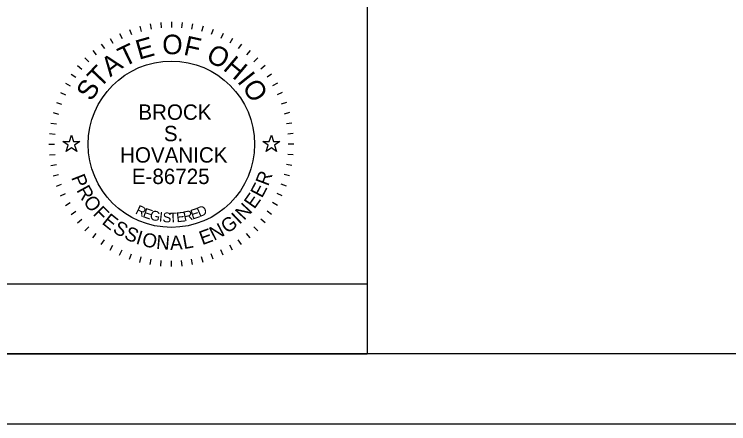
# Model space of a CAD drawing. Extents: x -3.6 to 34, y 0 to 32.8.
# Drawn here: x 23.88 to 28.99, y 0 to 2.93 of the extents above; entities that cross this region are included whole.
import ezdxf

# ---------------------------------------------------------------- set-up
doc = ezdxf.new("R2010")
doc.units = 0
for name, color, linetype in [('SH_Border', 7, 'Continuous'), ('SH_Cut_Line', 7, 'Continuous'), ('SH_Data', 7, 'Continuous'), ('SH_Seal', 7, 'Continuous')]:
    doc.layers.add(name, color=color, linetype=linetype)

msp = doc.modelspace()

# ---------------------------------------------------------------- linework, layer by layer
at = {"layer": 'SH_Border'}
msp.add_lwpolyline([(1.5, 21.5), (33.5, 21.5), (33.5, 0.5), (1.5, 0.5)], close=True, dxfattribs=at)
at = {"layer": 'SH_Cut_Line'}
msp.add_lwpolyline([(0, 0), (34, 0), (34, 22), (0, 22)], close=True, dxfattribs=at)
at = {"layer": 'SH_Data'}
for p in [(26.4, 3.75), (23.6, 0.5)]:
    msp.add_line(p, (26.4, 0.5), dxfattribs=at)
msp.add_lwpolyline([(23.6, 0.5), (23.6, 1), (26.4, 1), (26.4, 0.5)], close=True, dxfattribs=at)
at = {"layer": 'SH_Seal'}
for p, q in [((24.8481, 2.8617), (24.855, 2.8223)), ((24.9237, 2.8717), (24.9272, 2.8318)), ((25, 2.875), (25, 2.835)), ((25.0763, 2.8717), (25.0728, 2.8318)), ((25.1519, 2.8617), (25.145, 2.8223)), ((24.7007, 2.8222), (24.7144, 2.7846)), ((24.7735, 2.8452), (24.7839, 2.8065)), ((25.2265, 2.8452), (25.2161, 2.8065)), ((25.2993, 2.8222), (25.2856, 2.7846)), ((24.6302, 2.793), (24.6471, 2.7568)), ((25.3698, 2.793), (25.3529, 2.7568)), ((24.4981, 2.7168), (24.5211, 2.684)), ((24.5625, 2.7578), (24.5825, 2.7231)), ((25.4375, 2.7578), (25.4175, 2.7231)), ((25.5019, 2.7168), (25.4789, 2.684)), ((24.4376, 2.6703), (24.4633, 2.6396)), ((25.5624, 2.6703), (25.5367, 2.6396)), ((24.3813, 2.6187), (24.4096, 2.5904)), ((25.6187, 2.6187), (25.5904, 2.5904)), ((24.3297, 2.5624), (24.3604, 2.5367)), ((25.6703, 2.5624), (25.6396, 2.5367)), ((24.2832, 2.5019), (24.316, 2.4789)), ((25.7168, 2.5019), (25.684, 2.4789)), ((24.2422, 2.4375), (24.2769, 2.4175)), ((25.7578, 2.4375), (25.7231, 2.4175)), ((24.207, 2.3698), (24.2432, 2.3529)), ((25.793, 2.3698), (25.7568, 2.3529)), ((24.1778, 2.2993), (24.2154, 2.2856)), ((25.8222, 2.2993), (25.7846, 2.2856)), ((24.1548, 2.2265), (24.1935, 2.2161)), ((25.8452, 2.2265), (25.8065, 2.2161)), ((24.1383, 2.1519), (24.1777, 2.145)), ((25.8617, 2.1519), (25.8223, 2.145)), ((24.1283, 2.0763), (24.1682, 2.0728)), ((25.8717, 2.0763), (25.8318, 2.0728)), ((24.125, 2), (24.165, 2)), ((25.875, 2), (25.835, 2)), ((24.1283, 1.9237), (24.1682, 1.9272)), ((25.8717, 1.9237), (25.8318, 1.9272)), ((24.1383, 1.8481), (24.1777, 1.855)), ((25.8617, 1.8481), (25.8223, 1.855)), ((24.1548, 1.7735), (24.1935, 1.7839)), ((25.8452, 1.7735), (25.8065, 1.7839)), ((24.1778, 1.7007), (24.2154, 1.7144)), ((25.8222, 1.7007), (25.7846, 1.7144)), ((24.207, 1.6302), (24.2432, 1.6471)), ((25.793, 1.6302), (25.7568, 1.6471)), ((24.2422, 1.5625), (24.2769, 1.5825)), ((25.7578, 1.5625), (25.7231, 1.5825)), ((24.2832, 1.4981), (24.316, 1.5211)), ((25.7168, 1.4981), (25.684, 1.5211)), ((24.3297, 1.4376), (24.3604, 1.4633)), ((25.6703, 1.4376), (25.6396, 1.4633)), ((24.3813, 1.3813), (24.4096, 1.4096)), ((25.6187, 1.3813), (25.5904, 1.4096)), ((24.4376, 1.3297), (24.4633, 1.3604)), ((25.5624, 1.3297), (25.5367, 1.3604)), ((24.4981, 1.2832), (24.5211, 1.316)), ((25.5019, 1.2832), (25.4789, 1.316)), ((24.5625, 1.2422), (24.5825, 1.2769)), ((24.6302, 1.207), (24.6471, 1.2432)), ((25.3698, 1.207), (25.3529, 1.2432)), ((25.4375, 1.2422), (25.4175, 1.2769)), ((24.7007, 1.1778), (24.7144, 1.2154)), ((24.7735, 1.1548), (24.7839, 1.1935)), ((24.8481, 1.1383), (24.855, 1.1777)), ((25.1519, 1.1383), (25.145, 1.1777)), ((25.2265, 1.1548), (25.2161, 1.1935)), ((25.2993, 1.1778), (25.2856, 1.2154)), ((24.9237, 1.1283), (24.9272, 1.1682)), ((25, 1.125), (25, 1.165)), ((25.0763, 1.1283), (25.0728, 1.1682))]:
    msp.add_line(p, q, dxfattribs=at)
for points in [[(24.2236, 2.02), (24.2705, 2.02), (24.285, 2.0645), (24.2995, 2.02), (24.3464, 2.02), (24.3085, 1.9924), (24.323, 1.9478), (24.285, 1.9754), (24.247, 1.9478), (24.2615, 1.9924)], [(25.6536, 2.02), (25.7005, 2.02), (25.715, 2.0645), (25.7295, 2.02), (25.7764, 2.02), (25.7385, 1.9924), (25.753, 1.9478), (25.715, 1.9754), (25.677, 1.9478), (25.6915, 1.9924)]]:
    msp.add_lwpolyline(points, close=True, dxfattribs=at)
msp.add_circle((25, 2), 0.595, dxfattribs=at)

# ---------------------------------------------------------------- texts
for s, height, rotation, p in [('E', 0.14, 15.7571, (24.7684, 2.6038)), ('O', 0.14, 359.7812, (24.9347, 2.6443)), ('F', 0.14, 347.4362, (25.0811, 2.6417)), ('T', 0.14, 25.7167, (24.6616, 2.5518)), ('O', 0.14, 332.2586, (25.2398, 2.6015)), ('A', 0.14, 36.4747, (24.5634, 2.4781)), ('H', 0.14, 319.9136, (25.3632, 2.5361)), ('T', 0.14, 46.4344, (24.4883, 2.3964)), ('I', 0.14, 308.367, (25.4665, 2.4483)), ('S', 0.14, 57.1924, (24.4281, 2.3014)), ('O', 0.14, 303.1491, (25.5021, 2.4089)), ('P', 0.1, 291.494, (24.2823, 1.7621)), ('R', 0.1, 69.2322, (25.6919, 1.6954)), ('R', 0.1, 298.7311, (24.319, 1.6717)), ('E', 0.1, 61.9951, (25.6476, 1.6098)), ('E', 0.1, 54.758, (25.5933, 1.5314)), ('O', 0.1, 306.4666, (24.3655, 1.5883)), ('F', 0.1, 314.7068, (24.4343, 1.4983)), ('R', 0.07, 334.487, (24.7375, 1.5051)), ('E', 0.07, 341.04, (24.7906, 1.4801)), ('E', 0.07, 17.6836, (25.1498, 1.4602)), ('D', 0.07, 23.3052, (25.201, 1.477)), ('N', 0.1, 47.0224, (25.5202, 1.4508)), ('E', 0.1, 321.4393, (24.4978, 1.4348)), ('G', 0.07, 347.4752, (24.8414, 1.4618)), ('I', 0.07, 353.7858, (24.9091, 1.4468)), ('S', 0.07, 356.8926, (24.9358, 1.4429)), ('T', 0.07, 3.0061, (24.9857, 1.4387)), ('E', 0.07, 6.0117, (25.0389, 1.4412)), ('R', 0.07, 11.9184, (25.0925, 1.4474)), ('I', 0.1, 43.287, (25.4868, 1.4214)), ('S', 0.1, 328.6764, (24.5743, 1.3752)), ('N', 0.1, 27.3113, (25.3045, 1.3075)), ('G', 0.1, 35.0469, (25.3981, 1.357)), ('S', 0.1, 335.9134, (24.6564, 1.3266)), ('I', 0.1, 343.1505, (24.7406, 1.2897)), ('E', 0.1, 20.0742, (25.2212, 1.277)), ('O', 0.1, 346.8859, (24.7839, 1.2751)), ('N', 0.1, 355.1261, (24.8888, 1.2517)), ('A', 0.1, 2.8617, (24.9923, 1.2437)), ('L', 0.1, 10.0987, (25.0894, 1.249))]:
    msp.add_text(s, height=height, rotation=rotation, dxfattribs=at).set_placement(p)
for s, p in [('BROCK', (24.7639, 2.1749)), ('S.', (24.9465, 2.0216)), ('HOVANICK', (24.6332, 1.8684)), ('E-86725', (24.7173, 1.7151))]:
    msp.add_text(s, height=0.11, dxfattribs=at).set_placement(p)

doc.saveas('drawing.dxf')
